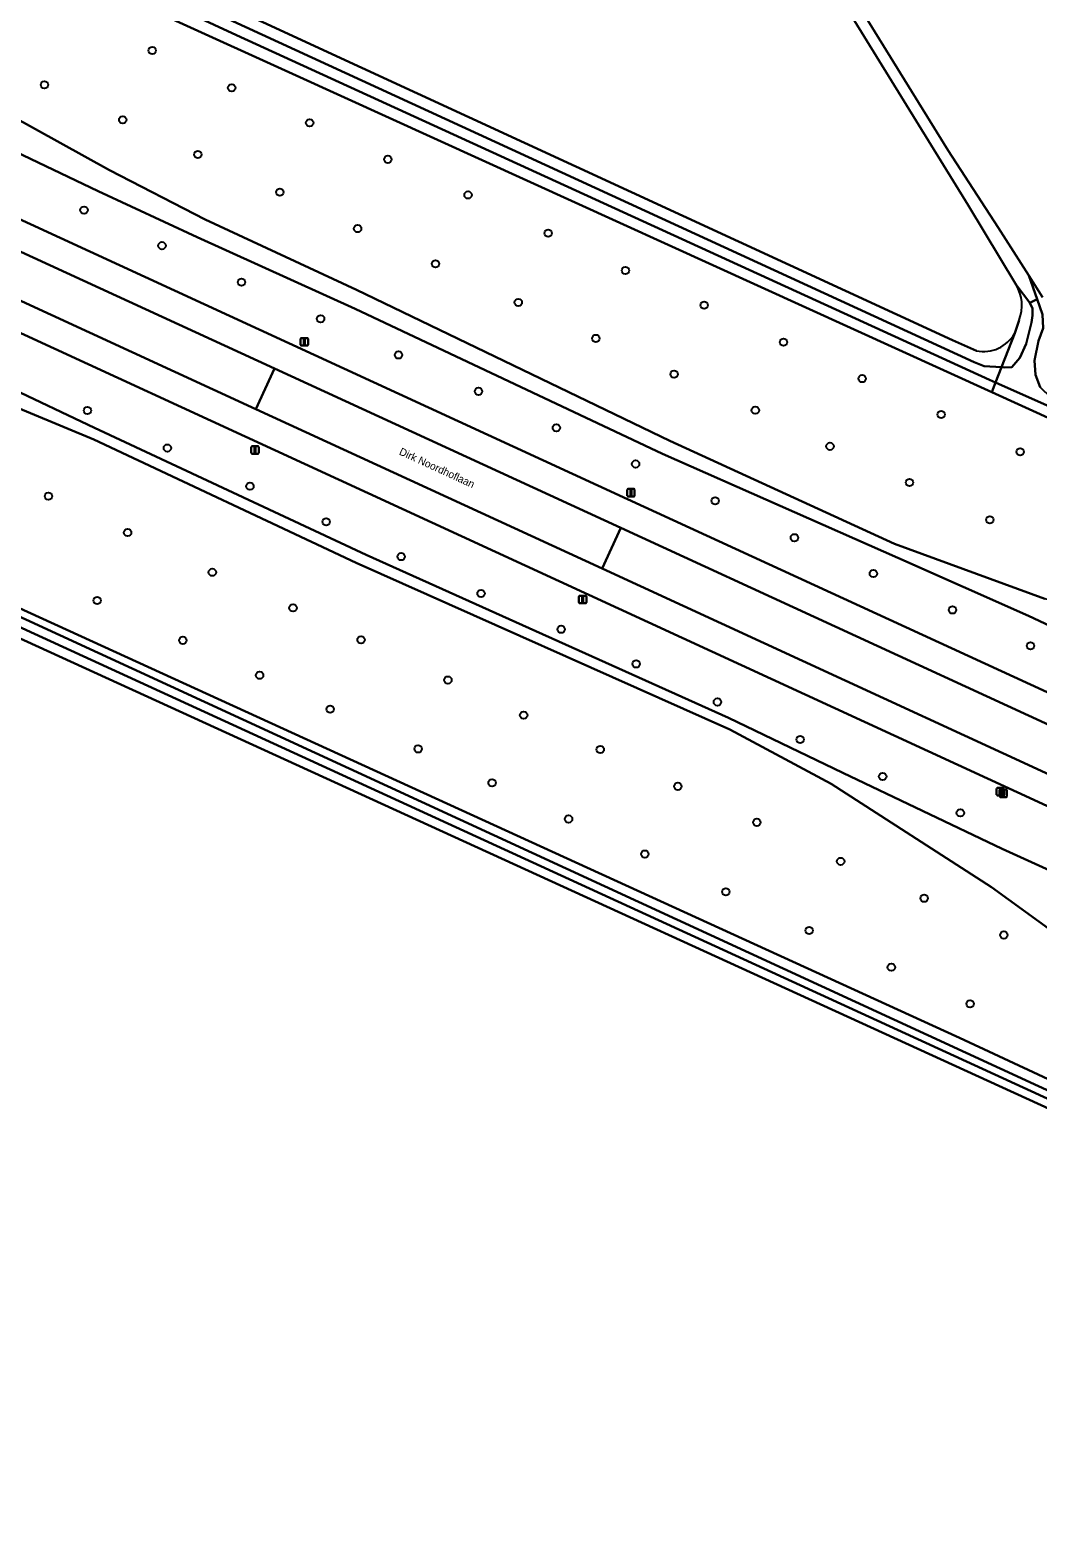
# Model space of a CAD drawing. Extents: x 155209 to 156748, y 385356 to 388487.
# Drawn here: x 155449 to 155582.4, y 387461.4 to 387660.8 of the extents above; entities that cross this region are included whole.
import ezdxf

# ---------------------------------------------------------------- set-up
doc = ezdxf.new("R2010")
doc.units = 0
for name, color, linetype in [('IMGEO_Berm_groen', 7, 'Continuous'), ('IMGEO_Berm_open', 7, 'Continuous'), ('IMGEO_Boom', 7, 'Continuous'), ('IMGEO_Bouwland', 7, 'Continuous'), ('IMGEO_Groenvoorziening', 7, 'Continuous'), ('IMGEO_Lichtmast', 7, 'Continuous'), ('IMGEO_Oever', 7, 'Continuous'), ('IMGEO_Openbare_ruimte_label', 7, 'Continuous'), ('IMGEO_Rijbaan_lokaal_gesloten', 7, 'Continuous'), ('IMGEO_Waterloop', 7, 'Continuous')]:
    doc.layers.add(name, color=color, linetype=linetype)

msp = doc.modelspace()

# ---------------------------------------------------------------- linework, layer by layer
at = {"layer": 'IMGEO_Berm_groen'}
for points in [[(155407.74, 387643.42), (155478.91, 387610.65), (155481.37, 387616.06), (155426.27, 387641.35)], [(155527.21, 387594.99), (155524.74, 387589.61), (155609.92, 387550.35)], [(155612.27, 387555.85), (155527.21, 387594.99)]]:
    msp.add_lwpolyline(points, dxfattribs=at)
at = {"layer": 'IMGEO_Berm_open'}
msp.add_lwpolyline([(155481.37, 387616.06), (155478.91, 387610.65), (155524.74, 387589.61), (155527.21, 387594.99)], close=True, dxfattribs=at)
at = {"layer": 'IMGEO_Boom'}
for centre in [(155465.18, 387658.1), (155450.91, 387653.56), (155475.69, 387653.17), (155461.27, 387648.93), (155486.01, 387648.53), (155471.22, 387644.34), (155496.36, 387643.71), (155482.07, 387639.38), (155506.97, 387639), (155456.15, 387637), (155492.36, 387634.55), (155517.57, 387633.94), (155466.47, 387632.29), (155502.67, 387629.9), (155527.8, 387629.01), (155476.99, 387627.47), (155513.62, 387624.79), (155538.22, 387624.42), (155487.46, 387622.63), (155523.88, 387620.03), (155497.77, 387617.84), (155548.72, 387619.54), (155534.24, 387615.29), (155559.12, 387614.71), (155508.35, 387613.03), (155456.6, 387610.49), (155544.99, 387610.53), (155569.58, 387609.97), (155518.66, 387608.21), (155554.87, 387605.76), (155467.18, 387605.53), (155580.04, 387605.02), (155529.15, 387603.42), (155478.11, 387600.48), (155565.4, 387600.98), (155451.44, 387599.16), (155539.67, 387598.55), (155488.19, 387595.77), (155576.02, 387596.03), (155461.92, 387594.35), (155550.16, 387593.67), (155498.11, 387591.17), (155473.13, 387589.1), (155560.61, 387588.93), (155508.69, 387586.3), (155457.89, 387585.37), (155483.81, 387584.39), (155571.08, 387584.12), (155469.22, 387580.1), (155492.81, 387580.16), (155519.29, 387581.56), (155581.41, 387579.38), (155529.22, 387576.98), (155479.39, 387575.48), (155504.31, 387574.85), (155539.97, 387571.95), (155488.73, 387571.01), (155514.33, 387570.21), (155550.93, 387566.98), (155500.36, 387565.74), (155524.47, 387565.66), (155561.84, 387562.1), (155510.15, 387561.26), (155534.74, 387560.79), (155520.28, 387556.47), (155545.19, 387556.03), (155572.12, 387557.28), (155530.37, 387551.84), (155556.28, 387550.87), (155541.08, 387546.84), (155567.33, 387545.99), (155552.12, 387541.73), (155577.87, 387541.13), (155562.99, 387536.87), (155573.41, 387532.04)]:
    msp.add_circle(centre, 0.489, dxfattribs=at)
at = {"layer": 'IMGEO_Bouwland'}
for points in [[(155597.12, 387897.54), (155557.58, 387873.01), (155515.31, 387846.69), (155465.7, 387815.6), (155481.79, 387788.65), (155491.53, 387773.04), (155515.51, 387734.32), (155548.91, 387679.86), (155570.49, 387644.86), (155577.11, 387634.68), (155581.17, 387628.37), (155582.99, 387625.47)], [(155490.25, 387772.25), (155480.51, 387787.87), (155464.43, 387814.8), (155450.63, 387805.88), (155414.67, 387782.62), (155414.49, 387782.52), (155407.07, 387778.48), (155402.98, 387773.67), (155383.2, 387759.36), (155382.71, 387759.03), (155383.07, 387758.45), (155383.71, 387758.83), (155399.21, 387732.45), (155416.92, 387703.3), (155427.92, 387685.79), (155492.9, 387655.83), (155571.1, 387619.78), (155574.25, 387618.39)], [(155579.5, 387627.13), (155573.16, 387637.67), (155547.63, 387679.07), (155514.23, 387733.53), (155490.25, 387772.25)], [(155688.41, 387564.9), (155687.85, 387563.57), (155687.39, 387562.46), (155683.29, 387564.19), (155576.27, 387612.9), (155484.23, 387654.8), (155384.77, 387699.96)], [(155443.17, 387651.3), (155459.51, 387642.3), (155472.17, 387635.77), (155492.21, 387626.46), (155533.66, 387606.49), (155563.42, 387592.86), (155583.32, 387585.58)], [(155579.31, 387620.72), (155579.9, 387622.46)], [(155584.75, 387541.29), (155576.23, 387547.46), (155555.02, 387561.13), (155541.61, 387568.3), (155492.15, 387590.36), (155457.45, 387606.65), (155444.55, 387612)], [(155679.2, 387478.17), (155675.14, 387479.3), (155674.79, 387478.07), (155674.48, 387476.99), (155672.26, 387477.78), (155393.15, 387605.27), (155387.83, 387608.06), (155384.83, 387609.49), (155384.03, 387607.48), (155379.35, 387595.71), (155376.57, 387589.51), (155370.49, 387581.65), (155370.05, 387581.29), (155370.49, 387570.86), (155371.44, 387548.9), (155372.76, 387510.61), (155391.2, 387477.88), (155390.94, 387473.12), (155386.93, 387471.43), (155377.81, 387467.6), (155380.5, 387367.97)], [(155404.91, 387603.85), (155572.02, 387527.55), (155670.99, 387481.41), (155675.14, 387479.3), (155679.2, 387478.17), (155679.2, 387479.43), (155679.21, 387480.83), (155679.53, 387482.21), (155679.73, 387483.03), (155679.97, 387484.04), (155680.51, 387496.63), (155680.97, 387501.97), (155681.5, 387508.04), (155683.19, 387520.36), (155685.19, 387533.25), (155687.3, 387543.73)]]:
    msp.add_lwpolyline(points, dxfattribs=at)
for centre, radius, start, end in [((155574.96, 387624.39), 5.3, 338.7189, 31.1559), ((155575.18, 387623.03), 4.74, 258.6778, 330.7072)]:
    msp.add_arc(centre, radius, start, end, dxfattribs=at)
at = {"layer": 'IMGEO_Groenvoorziening'}
for points in [[(155412.68, 387659.27), (155421.79, 387656.19), (155430.62, 387652.37), (155442.12, 387647.09), (155458.04, 387639.49), (155471.14, 387633.43), (155492.04, 387623.95), (155532.71, 387604.77), (155563.84, 387591.01), (155581.15, 387583.34), (155584.82, 387581.6), (155600.55, 387574.49), (155613.36, 387568.6)], [(155613.36, 387568.6), (155600.55, 387574.49), (155584.82, 387581.6), (155581.15, 387583.34), (155563.84, 387591.01), (155532.71, 387604.77), (155492.04, 387623.95), (155471.14, 387633.43), (155458.04, 387639.49), (155442.12, 387647.09), (155430.62, 387652.37), (155421.79, 387656.19), (155412.68, 387659.27)], [(155655.59, 387555.59), (155654.51, 387556.89), (155643.66, 387562.28), (155637.04, 387566.92), (155630.52, 387570.85), (155623.19, 387574.28), (155613.17, 387577.54), (155602.84, 387580.68), (155583.32, 387585.58), (155563.42, 387592.86), (155533.66, 387606.49), (155492.21, 387626.46), (155472.17, 387635.77), (155459.51, 387642.3), (155443.17, 387651.3)], [(155430.55, 387643.66), (155528.09, 387598.76), (155612.21, 387560.13)], [(155608.29, 387546.85), (155522.96, 387586.13), (155406.67, 387639.64)], [(155592.12, 387545.97), (155577.64, 387552.52), (155556.55, 387562.59), (155541.42, 387569.85), (155493.51, 387591.42), (155457.54, 387608.21), (155446.04, 387613.65)], [(155446.04, 387613.65), (155457.54, 387608.21), (155493.51, 387591.42), (155541.42, 387569.85), (155556.55, 387562.59), (155577.64, 387552.52), (155592.12, 387545.97)], [(155444.55, 387612), (155457.45, 387606.65), (155492.15, 387590.36), (155541.61, 387568.3), (155555.02, 387561.13), (155576.23, 387547.46), (155584.75, 387541.29)]]:
    msp.add_lwpolyline(points, dxfattribs=at)
at = {"layer": 'IMGEO_Lichtmast'}
for p, q in [((155484.81, 387619.17), (155484.81, 387619.97)), ((155484.81, 387619.97), (155484.81, 387619.17)), ((155484.91, 387620.07), (155485.7, 387620.07)), ((155485.7, 387620.07), (155484.91, 387620.07)), ((155485.7, 387619.07), (155484.91, 387619.07)), ((155484.91, 387619.07), (155485.7, 387619.07)), ((155485.8, 387619.97), (155485.8, 387619.17)), ((155485.8, 387619.17), (155485.8, 387619.97)), ((155478.28, 387604.86), (155478.28, 387605.66)), ((155478.28, 387605.66), (155478.28, 387604.86)), ((155478.38, 387605.76), (155479.17, 387605.76)), ((155479.17, 387605.76), (155478.38, 387605.76)), ((155479.17, 387604.76), (155478.38, 387604.76)), ((155478.38, 387604.76), (155479.17, 387604.76)), ((155479.27, 387605.66), (155479.27, 387604.86)), ((155479.27, 387604.86), (155479.27, 387605.66)), ((155528.04, 387599.22), (155528.04, 387600.02)), ((155528.04, 387600.02), (155528.04, 387599.22)), ((155528.14, 387600.12), (155528.92, 387600.12)), ((155528.92, 387600.12), (155528.14, 387600.12)), ((155528.92, 387599.12), (155528.14, 387599.12)), ((155528.14, 387599.12), (155528.92, 387599.12)), ((155529.02, 387600.02), (155529.02, 387599.22)), ((155529.02, 387599.22), (155529.02, 387600.02)), ((155521.65, 387585.1), (155521.65, 387585.9)), ((155521.65, 387585.9), (155521.65, 387585.1)), ((155521.75, 387586), (155522.54, 387586)), ((155522.54, 387586), (155521.75, 387586)), ((155522.54, 387585), (155521.75, 387585)), ((155521.75, 387585), (155522.54, 387585)), ((155522.64, 387585.9), (155522.64, 387585.1)), ((155522.64, 387585.1), (155522.64, 387585.9)), ((155576.91, 387559.69), (155576.91, 387560.49)), ((155576.91, 387560.49), (155576.91, 387559.69)), ((155577.01, 387560.59), (155577.8, 387560.59)), ((155577.8, 387560.59), (155577.01, 387560.59)), ((155577.4, 387560.38), (155578.19, 387560.38)), ((155578.19, 387560.38), (155577.4, 387560.38)), ((155577.9, 387560.49), (155577.9, 387559.69)), ((155577.9, 387559.69), (155577.9, 387560.49)), ((155577.8, 387559.59), (155577.01, 387559.59)), ((155577.01, 387559.59), (155577.8, 387559.59)), ((155577.3, 387559.48), (155577.3, 387560.28)), ((155577.3, 387560.28), (155577.3, 387559.48)), ((155578.19, 387559.38), (155577.4, 387559.38)), ((155577.4, 387559.38), (155578.19, 387559.38)), ((155578.29, 387560.28), (155578.29, 387559.48)), ((155578.29, 387559.48), (155578.29, 387560.28))]:
    msp.add_line(p, q, dxfattribs=at)
for points in [[(155485.23, 387619.94), (155485.38, 387619.94), (155485.38, 387619.19), (155485.23, 387619.19), (155485.23, 387619.94)], [(155478.7, 387605.63), (155478.85, 387605.63), (155478.85, 387604.88), (155478.7, 387604.88), (155478.7, 387605.63)], [(155528.46, 387600), (155528.61, 387600), (155528.61, 387599.25), (155528.46, 387599.25), (155528.46, 387600)], [(155522.07, 387585.87), (155522.22, 387585.87), (155522.22, 387585.12), (155522.07, 387585.12), (155522.07, 387585.87)], [(155577.33, 387560.47), (155577.48, 387560.47), (155577.48, 387559.72), (155577.33, 387559.72), (155577.33, 387560.47)], [(155577.72, 387560.26), (155577.87, 387560.26), (155577.87, 387559.51), (155577.72, 387559.51), (155577.72, 387560.26)]]:
    msp.add_lwpolyline(points, dxfattribs=at)
for centre, start, end in [((155484.91, 387619.97), 90, 180), ((155484.91, 387619.97), 90, 180), ((155484.91, 387619.17), 180, 270), ((155484.91, 387619.17), 180, 270), ((155485.7, 387619.97), 0, 90), ((155485.7, 387619.97), 360, 90), ((155485.7, 387619.17), 270, 0), ((155485.7, 387619.17), 270, 0), ((155478.38, 387605.66), 90, 180), ((155478.38, 387605.66), 90, 180), ((155478.38, 387604.86), 180, 270), ((155478.38, 387604.86), 180, 270), ((155479.17, 387605.66), 0, 90), ((155479.17, 387605.66), 360, 90), ((155479.17, 387604.86), 270, 0), ((155479.17, 387604.86), 270, 0), ((155528.14, 387600.02), 90, 180), ((155528.14, 387600.02), 90, 180), ((155528.14, 387599.22), 180, 270), ((155528.14, 387599.22), 180, 270), ((155528.92, 387600.02), 0, 90), ((155528.92, 387600.02), 360, 90), ((155528.92, 387599.22), 270, 0), ((155528.92, 387599.22), 270, 0), ((155521.75, 387585.9), 90, 180), ((155521.75, 387585.9), 90, 180), ((155521.75, 387585.1), 180, 270), ((155521.75, 387585.1), 180, 270), ((155522.54, 387585.9), 0, 90), ((155522.54, 387585.9), 360, 90), ((155522.54, 387585.1), 270, 0), ((155522.54, 387585.1), 270, 0), ((155577.01, 387560.49), 90, 180), ((155577.01, 387560.49), 90, 180), ((155577.4, 387560.28), 90, 180), ((155577.4, 387560.28), 90, 180), ((155577.8, 387560.49), 0, 90), ((155577.8, 387560.49), 360, 90), ((155578.19, 387560.28), 0, 90), ((155578.19, 387560.28), 360, 90), ((155577.01, 387559.69), 180, 270), ((155577.01, 387559.69), 180, 270), ((155577.4, 387559.48), 180, 270), ((155577.4, 387559.48), 180, 270), ((155577.8, 387559.69), 270, 0), ((155577.8, 387559.69), 270, 0), ((155578.19, 387559.48), 270, 0), ((155578.19, 387559.48), 270, 0)]:
    msp.add_arc(centre, 0.1, start, end, dxfattribs=at)
at = {"layer": 'IMGEO_Oever'}
for points in [[(155574.25, 387618.39), (155571.1, 387619.78), (155492.9, 387655.83), (155427.92, 387685.79), (155425.42, 387686.93), (155386.66, 387704.8)], [(155576.27, 387612.9), (155576.78, 387614.21), (155575.97, 387614.57), (155518.63, 387640.78), (155476.31, 387660.15), (155450.97, 387671.91), (155387.58, 387700.55), (155388.58, 387702.11), (155426.98, 387684.45), (155429.47, 387683.31), (155573.93, 387616.87), (155575.29, 387616.34), (155577.56, 387616.22), (155579.31, 387620.72)], [(155384.77, 387699.96), (155484.23, 387654.8), (155576.27, 387612.9)], [(155582.99, 387625.47), (155581.17, 387628.37), (155582.3, 387625.23), (155583, 387623.17), (155583.06, 387621.39), (155582.47, 387619.71), (155581.95, 387617.1), (155582.08, 387615.21), (155582.69, 387613.6), (155584.11, 387612.23), (155687.62, 387564.31), (155687.43, 387563.76), (155687.3, 387563.36), (155583.63, 387611.17), (155576.78, 387614.21)], [(155579.31, 387620.72), (155577.56, 387616.22), (155577.98, 387616.2), (155578.95, 387616.22), (155580.01, 387617.45), (155580.82, 387619.33), (155581.52, 387622.15), (155581.66, 387623.07), (155581.65, 387623.98), (155581.32, 387624.73), (155579.5, 387627.13)], [(155579.9, 387622.46), (155579.31, 387620.72)], [(155576.78, 387614.21), (155576.27, 387612.9), (155683.29, 387564.19), (155687.39, 387562.46), (155687.85, 387563.57), (155688.41, 387564.9), (155591.11, 387610.32), (155585.91, 387612.95)]]:
    msp.add_lwpolyline(points, dxfattribs=at)
for points in [[(155388.99, 387611.34), (155387.83, 387608.06), (155393.15, 387605.27), (155672.26, 387477.78), (155674.48, 387476.99), (155674.79, 387478.07), (155675.14, 387479.3), (155670.99, 387481.41), (155572.02, 387527.55), (155404.91, 387603.85)], [(155389.83, 387609.71), (155390.96, 387609.31), (155673.1, 387479.4), (155674.43, 387478.76), (155674.56, 387478.53), (155674.45, 387478.23), (155674.39, 387478.09), (155674.2, 387478), (155673.22, 387478.41), (155392.18, 387607.27), (155389.41, 387608.65)]]:
    msp.add_lwpolyline(points, close=True, dxfattribs=at)
for centre, radius, start, end in [((155574.96, 387624.39), 5.3, 338.7189, 31.1559), ((155575.18, 387623.03), 4.74, 258.6778, 330.7072)]:
    msp.add_arc(centre, radius, start, end, dxfattribs=at)
at = {"layer": 'IMGEO_Rijbaan_lokaal_gesloten'}
for points in [[(155609.92, 387550.35), (155524.74, 387589.61), (155478.91, 387610.65), (155407.74, 387643.42)], [(155612.21, 387560.13), (155528.09, 387598.76), (155430.55, 387643.66)], [(155426.27, 387641.35), (155481.37, 387616.06), (155527.21, 387594.99), (155612.27, 387555.85)], [(155406.67, 387639.64), (155522.96, 387586.13), (155608.29, 387546.85)]]:
    msp.add_lwpolyline(points, dxfattribs=at)
at = {"layer": 'IMGEO_Waterloop'}
for points in [[(155515.51, 387734.32), (155491.53, 387773.04), (155481.79, 387788.65), (155465.7, 387815.6), (155464.43, 387814.8), (155480.51, 387787.87), (155490.25, 387772.25), (155514.23, 387733.53), (155547.63, 387679.07), (155573.16, 387637.67), (155579.5, 387627.13), (155581.32, 387624.73), (155582.3, 387625.23), (155581.17, 387628.37), (155577.11, 387634.68), (155570.49, 387644.86), (155548.91, 387679.86)], [(155576.78, 387614.21), (155577.56, 387616.22), (155575.29, 387616.34), (155573.93, 387616.87), (155429.47, 387683.31), (155426.98, 387684.45), (155388.58, 387702.11), (155387.58, 387700.55), (155450.97, 387671.91), (155476.31, 387660.15), (155518.63, 387640.78), (155575.97, 387614.57)], [(155577.56, 387616.22), (155576.78, 387614.21), (155583.63, 387611.17), (155687.3, 387563.36), (155687.43, 387563.76), (155687.62, 387564.31), (155584.11, 387612.23), (155582.69, 387613.6), (155582.08, 387615.21), (155581.95, 387617.1), (155582.47, 387619.71), (155583.06, 387621.39), (155583, 387623.17), (155582.3, 387625.23), (155581.32, 387624.73), (155581.65, 387623.98), (155581.66, 387623.07), (155581.52, 387622.15), (155580.82, 387619.33), (155580.01, 387617.45), (155578.95, 387616.22), (155577.98, 387616.2)], [(155390.96, 387609.31), (155389.83, 387609.71), (155389.41, 387608.65), (155392.18, 387607.27), (155673.22, 387478.41), (155674.2, 387478), (155674.39, 387478.09), (155674.45, 387478.23), (155674.56, 387478.53), (155674.43, 387478.76), (155673.1, 387479.4)]]:
    msp.add_lwpolyline(points, close=True, dxfattribs=at)

# ---------------------------------------------------------------- texts
at = {"layer": 'IMGEO_Openbare_ruimte_label'}
msp.add_text('Dirk Noordhoflaan', height=1, rotation=335.3569, dxfattribs=at).set_placement((155497.76, 387604.71))

doc.saveas('drawing.dxf')
